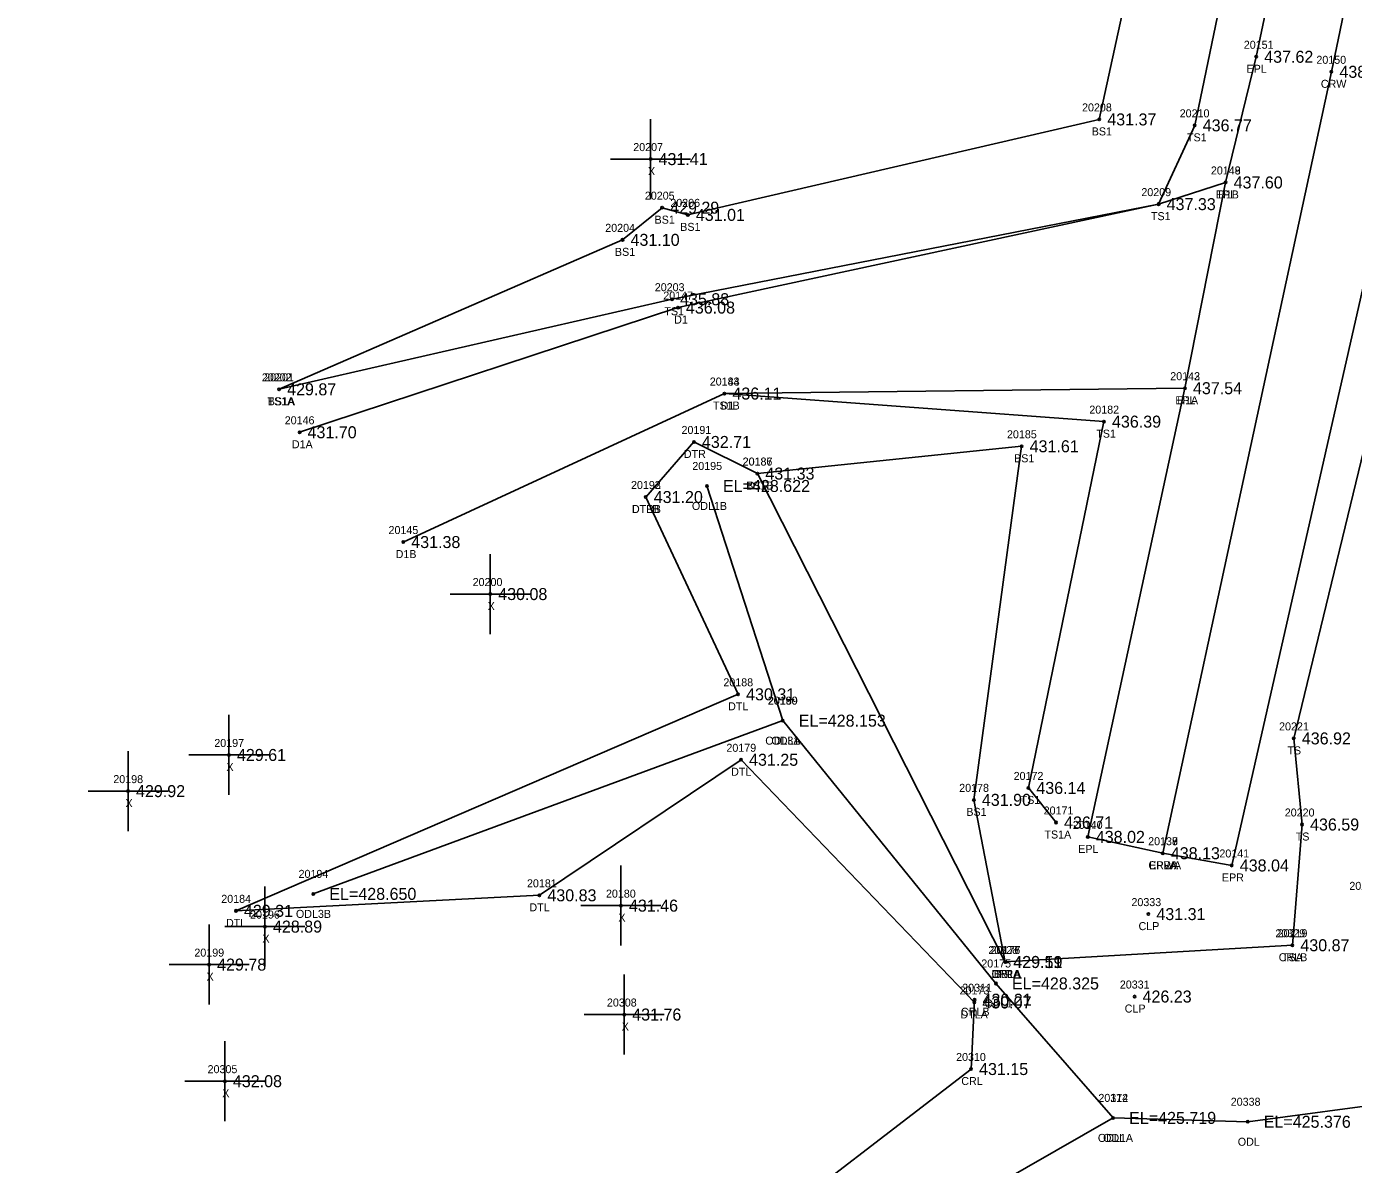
# Model space of a CAD drawing. Extents: x 1755707 to 1756750, y 975854 to 977363.
# Drawn here: x 1756070.3 to 1756236.1, y 976608 to 976750.2 of the extents above; entities that cross this region are included whole.
import ezdxf

# ---------------------------------------------------------------- set-up
doc = ezdxf.new("R2010")
doc.units = 0
for name, color, linetype in [('RD_DTM_BkLn1', 7, 'Continuous'), ('RD_DTM_BkLn2', 7, 'Continuous'), ('RD_DTM_BkLn_txCode', 7, 'Continuous'), ('RD_EX_Driveway', 7, 'Continuous'), ('RD_EX_Driveway_txCode', 7, 'Continuous'), ('RD_EX_H2O', 7, 'Continuous'), ('RD_EX_H2O_txCode', 7, 'Continuous'), ('RD_EX_Misc', 7, 'Continuous'), ('RD_EX_Misc_txCode', 7, 'Continuous'), ('RD_EX_Road', 7, 'Continuous'), ('RD_EX_Road_txCode', 7, 'Continuous'), ('RD_EX_TX_Driveway_ELEV', 7, 'Continuous'), ('RD_EX_TX_H2O_ELEV', 7, 'Continuous'), ('RD_EX_TX_Misc_ELEV', 7, 'Continuous'), ('RD_EX_TX_Road_ELEV', 7, 'Continuous'), ('RD_HC_Survey_ELEV', 7, 'Continuous'), ('RD_HC_Survey_txCode', 7, 'Continuous'), ('RD_SMD_Locator', 7, 'Continuous')]:
    doc.layers.add(name, color=color, linetype=linetype)

msp = doc.modelspace()

# ---------------------------------------------------------------- linework, layer by layer
at = {"layer": 'RD_DTM_BkLn1'}
msp.add_lwpolyline([(1756212.24, 976646.92), (1756233.31, 976744.58), (1756253.87, 976843.36), (1756274.18, 976942.87), (1756294.7, 977044.28), (1756314.7, 977141.54), (1756335.65, 977241.96), (1756357.9, 977342.03)], dxfattribs=at)
at = {"layer": 'RD_DTM_BkLn2'}
for points in [[(1756101.82, 976704.9), (1756150.92, 976716.16), (1756211.72, 976728.04), (1756216.23, 976737.89), (1756238.86, 976847.03), (1756261.79, 976945.44), (1756283.19, 977044.99), (1756303.06, 977145.95), (1756325.46, 977245.55), (1756346.55, 977344.09)], [(1756101.82, 976704.9), (1756144.73, 976723.58), (1756149.68, 976727.6), (1756152.89, 976726.7), (1756204.3, 976738.63), (1756228.54, 976849.91), (1756252.92, 976947.37), (1756266.62, 977008.29)], [(1756228.43, 976635.42), (1756229.64, 976650.51), (1756228.61, 976661.27), (1756248.15, 976741.84), (1756270.72, 976839.45), (1756280.12, 976897.48), (1756286.17, 976899.18), (1756290.15, 976895.42)], [(1756198.9, 976650.76), (1756195.44, 976655.08), (1756204.89, 976700.86), (1756157.46, 976704.37)], [(1756192.56, 976633.32), (1756188.63, 976653.59), (1756194.6, 976697.78), (1756161.58, 976694.37)]]:
    msp.add_lwpolyline(points, dxfattribs=at)
at = {"layer": 'RD_EX_Driveway'}
msp.add_line((1756211.72, 976728.04), (1756220.09, 976730.75), dxfattribs=at)
for points in [[(1756104.37, 976699.53), (1756151.65, 976715.11), (1756211.72, 976728.04)], [(1756215.01, 976705.04), (1756157.46, 976704.37), (1756117.33, 976685.81)]]:
    msp.add_lwpolyline(points, dxfattribs=at)
at = {"layer": 'RD_EX_H2O'}
for p, q in [((1756164.75, 976663.49), (1756106.09, 976641.84)), ((1756192.55, 976633.33), (1756228.43, 976635.42))]:
    msp.add_line(p, q, dxfattribs=at)
for points in [[(1756192.56, 976633.32), (1756161.58, 976694.37), (1756153.65, 976698.32), (1756147.63, 976691.44)], [(1756206.03, 976613.84), (1756191.39, 976630.64), (1756164.75, 976663.49), (1756155.28, 976692.82)], [(1756188.69, 976628.27), (1756159.54, 976658.6), (1756134.34, 976641.66), (1756096.42, 976639.72), (1756159.17, 976666.78), (1756147.63, 976691.44)], [(1755737.32, 976440.59), (1755791.96, 976465.24), (1755883.28, 976455.13), (1755971.27, 976482.19), (1756023.59, 976552.72), (1756109.16, 976576.08), (1756159.34, 976597.67), (1756188.28, 976619.95), (1756188.72, 976628.61)], [(1755742.06, 976428.66), (1755806.09, 976451.93), (1755887.6, 976439.2), (1755982.53, 976463.01), (1756033.69, 976542.66), (1756128.83, 976549.6), (1756169.54, 976582.49), (1756188.08, 976603.54), (1756206.03, 976613.84), (1756222.85, 976613.36), (1756242.15, 976615.93), (1756317.48, 976609.64), (1756394.89, 976590.11), (1756422.33, 976593.66), (1756518.23, 976582.93), (1756609.24, 976524.24), (1756704.51, 976490.62)]]:
    msp.add_lwpolyline(points, dxfattribs=at)
at = {"layer": 'RD_EX_Misc'}
for p, q in [((1756148.23, 976728.67), (1756148.23, 976738.67)), ((1756143.23, 976733.67), (1756153.23, 976733.67)), ((1756128.2, 976674.31), (1756128.2, 976684.31)), ((1756123.2, 976679.31), (1756133.2, 976679.31)), ((1756095.55, 976654.2), (1756095.55, 976664.2)), ((1756082.94, 976649.68), (1756082.94, 976659.68)), ((1756090.55, 976659.2), (1756100.55, 976659.2)), ((1756077.94, 976654.68), (1756087.94, 976654.68)), ((1756144.53, 976635.37), (1756144.53, 976645.37)), ((1756100.05, 976632.75), (1756100.05, 976642.75)), ((1756139.53, 976640.37), (1756149.53, 976640.37)), ((1756093.07, 976628), (1756093.07, 976638)), ((1756095.05, 976637.75), (1756105.05, 976637.75)), ((1756088.07, 976633), (1756098.07, 976633)), ((1756144.94, 976621.76), (1756144.94, 976631.76)), ((1756139.94, 976626.76), (1756149.94, 976626.76)), ((1756095.04, 976613.43), (1756095.04, 976623.43)), ((1756090.04, 976618.43), (1756100.04, 976618.43))]:
    msp.add_line(p, q, dxfattribs=at)
at = {"layer": 'RD_EX_Road'}
for points in [[(1756212.24, 976646.92), (1756202.87, 976648.96), (1756215.01, 976705.04), (1756220.09, 976730.75), (1756223.91, 976746.46), (1756244.6, 976844.81), (1756265.35, 976944.71), (1756286.1, 977045.83), (1756306.04, 977143.32), (1756326.71, 977243.79), (1756348.97, 977343.58)], [(1756212.24, 976646.92), (1756220.86, 976645.39), (1756242.73, 976741.74), (1756264.15, 976840.28), (1756284.31, 976940.54), (1756305.17, 977042.39), (1756325.03, 977140.07), (1756346.16, 977239.41), (1756368.47, 977341.2)]]:
    msp.add_lwpolyline(points, dxfattribs=at)
at = {"layer": 'RD_SMD_Locator'}
for centre in [(1756223.91, 976746.46), (1756233.31, 976744.58), (1756204.3, 976738.63), (1756216.23, 976737.89), (1756148.23, 976733.67), (1756220.09, 976730.75), (1756220.09, 976730.75), (1756211.72, 976728.04), (1756149.68, 976727.6), (1756152.89, 976726.7), (1756144.73, 976723.58), (1756150.92, 976716.16), (1756151.65, 976715.11), (1756101.82, 976704.9), (1756101.82, 976704.9), (1756215.01, 976705.04), (1756215.01, 976705.04), (1756157.46, 976704.37), (1756157.46, 976704.37), (1756204.89, 976700.86), (1756104.37, 976699.53), (1756153.65, 976698.32), (1756194.6, 976697.78), (1756161.58, 976694.37), (1756161.58, 976694.37), (1756147.63, 976691.44), (1756147.63, 976691.44), (1756155.28, 976692.82), (1756117.33, 976685.81), (1756128.2, 976679.31), (1756159.17, 976666.78), (1756164.75, 976663.49), (1756164.75, 976663.49), (1756228.61, 976661.27), (1756095.55, 976659.2), (1756159.54, 976658.6), (1756195.44, 976655.08), (1756082.94, 976654.68), (1756188.63, 976653.59), (1756198.9, 976650.76), (1756229.64, 976650.51), (1756202.87, 976648.96), (1756212.24, 976646.92), (1756212.24, 976646.92), (1756212.24, 976646.92), (1756220.86, 976645.39), (1756106.09, 976641.84), (1756134.34, 976641.66), (1756144.53, 976640.37), (1756096.42, 976639.72), (1756210.44, 976639.31), (1756100.05, 976637.75), (1756228.43, 976635.42), (1756228.43, 976635.42), (1756093.07, 976633), (1756192.55, 976633.33), (1756192.56, 976633.32), (1756192.56, 976633.32), (1756191.39, 976630.64), (1756188.72, 976628.61), (1756208.71, 976629.01), (1756188.69, 976628.27), (1756144.94, 976626.76), (1756188.28, 976619.95), (1756095.04, 976618.43), (1756206.03, 976613.84), (1756206.03, 976613.84), (1756222.85, 976613.36)]:
    msp.add_circle(centre, 0.15, dxfattribs=at)

# ---------------------------------------------------------------- texts
at = {"layer": 'RD_DTM_BkLn_txCode'}
for s, p in [('20208', (1756202.15, 976739.63)), ('20210', (1756214.35, 976738.89)), ('BS1', (1756203.36, 976736.63)), ('TS1', (1756215.27, 976735.89)), ('20209', (1756209.56, 976729.04)), ('20205', (1756147.52, 976728.6)), ('20206', (1756150.7, 976727.7)), ('BS1', (1756148.73, 976725.6)), ('TS1', (1756210.76, 976726.04)), ('20204', (1756142.57, 976724.58)), ('BS1', (1756151.94, 976724.7)), ('BS1', (1756143.78, 976721.58)), ('20203', (1756148.76, 976717.16)), ('TS1', (1756149.96, 976714.16)), ('20202', (1756099.66, 976705.9)), ('20201', (1756099.95, 976705.9)), ('20183', (1756155.63, 976705.37)), ('TS1A', (1756100.37, 976702.9)), ('BS1A', (1756100.39, 976702.9)), ('TS1B', (1756156.03, 976702.37)), ('20182', (1756203.06, 976701.86)), ('TS1', (1756203.93, 976698.86)), ('20185', (1756192.77, 976698.78)), ('BS1', (1756193.66, 976695.78)), ('20186', (1756159.73, 976695.37)), ('BS1B', (1756160.17, 976692.37)), ('20221', (1756226.77, 976662.27)), ('TS', (1756227.81, 976659.27)), ('20172', (1756193.6, 976656.08)), ('20178', (1756186.8, 976654.59)), ('TS1', (1756194.48, 976653.08)), ('BS1', (1756187.69, 976651.59)), ('20171', (1756197.35, 976651.76)), ('20220', (1756227.48, 976651.51)), ('TS1A', (1756197.45, 976648.76)), ('TS', (1756228.85, 976648.51)), ('20219', (1756226.59, 976636.42)), ('20176', (1756190.71, 976634.32)), ('TSA', (1756227.14, 976633.42)), ('BS1A', (1756191.13, 976631.32))]:
    msp.add_text(s, height=1, dxfattribs=at).set_placement(p)
at = {"layer": 'RD_EX_Driveway_txCode'}
for s, p in [('20148', (1756218.25, 976731.75)), ('D1B', (1756219.14, 976728.75)), ('20147', (1756149.82, 976716.11)), ('D1', (1756151.18, 976713.11)), ('20143', (1756213.17, 976706.04)), ('20144', (1756155.63, 976705.37)), ('D1', (1756156.99, 976702.37)), ('D1A', (1756214.05, 976703.04)), ('20146', (1756102.52, 976700.53)), ('D1A', (1756103.41, 976697.53)), ('20145', (1756115.49, 976686.81)), ('D1B', (1756116.38, 976683.81))]:
    msp.add_text(s, height=1, dxfattribs=at).set_placement(p)
at = {"layer": 'RD_EX_H2O_txCode'}
for s, p in [('20191', (1756152.1, 976699.32)), ('DTR', (1756152.39, 976696.32)), ('20195', (1756153.45, 976694.82)), ('20187', (1756159.75, 976695.37)), ('20192', (1756145.79, 976692.44)), ('20193', (1756145.79, 976692.44)), ('DTR', (1756160.32, 976692.37)), ('DTRB', (1756145.89, 976689.44)), ('DTLB', (1756145.91, 976689.44)), ('ODL1B', (1756153.4, 976689.82)), ('20188', (1756157.33, 976667.78)), ('DTL', (1756157.92, 976664.78)), ('20190', (1756162.87, 976665.49)), ('20189', (1756162.91, 976665.49)), ('20179', (1756157.71, 976659.6)), ('ODL3A', (1756162.57, 976660.49)), ('ODL1', (1756163.34, 976660.49)), ('DTL', (1756158.3, 976656.6)), ('20194', (1756104.25, 976643.84)), ('20181', (1756132.79, 976642.66)), ('20224', (1756235.55, 976642.34)), ('20184', (1756094.59, 976640.72)), ('DTL', (1756133.09, 976639.66)), ('DTL', (1756095.18, 976637.72)), ('ODL3B', (1756103.92, 976638.84)), ('20329', (1756226.31, 976636.42)), ('20328', (1756190.44, 976634.33)), ('20177', (1756190.73, 976634.32)), ('20175', (1756189.56, 976632.64)), ('CRLB', (1756226.73, 976633.42)), ('CRLA', (1756190.84, 976631.33)), ('DTRA', (1756190.81, 976631.32)), ('20173', (1756186.85, 976629.27)), ('20311', (1756187.17, 976629.61)), ('ODL1', (1756189.98, 976627.64)), ('DTLA', (1756186.95, 976626.27)), ('CRLB', (1756187.02, 976626.61)), ('20310', (1756186.41, 976620.95)), ('CRL', (1756187.06, 976617.95)), ('20174', (1756204.19, 976615.84)), ('20312', (1756204.19, 976615.84)), ('20338', (1756220.73, 976615.36)), ('ODL1A', (1756204.13, 976610.84)), ('ODL', (1756204.78, 976610.84)), ('ODL', (1756221.61, 976610.36))]:
    msp.add_text(s, height=1, dxfattribs=at).set_placement(p)
at = {"layer": 'RD_EX_Misc_txCode'}
for s, p in [('20207', (1756146.07, 976734.67)), ('X', (1756147.91, 976731.67)), ('20200', (1756126, 976680.31)), ('X', (1756127.88, 976677.31)), ('20197', (1756093.72, 976660.2)), ('X', (1756095.24, 976657.2)), ('20198', (1756081.1, 976655.68)), ('X', (1756082.62, 976652.68)), ('20180', (1756142.66, 976641.37)), ('20196', (1756098.19, 976638.75)), ('X', (1756144.21, 976638.37)), ('X', (1756099.73, 976635.75)), ('20199', (1756091.23, 976634)), ('X', (1756092.75, 976631)), ('20308', (1756142.78, 976627.76)), ('X', (1756144.63, 976624.76)), ('20305', (1756092.88, 976619.43)), ('X', (1756094.72, 976616.43))]:
    msp.add_text(s, height=1, dxfattribs=at).set_placement(p)
at = {"layer": 'RD_EX_Road_txCode'}
for s, p in [('20151', (1756222.36, 976747.46)), ('EPL', (1756222.7, 976744.46)), ('20149', (1756218.25, 976731.75)), ('EPL', (1756218.88, 976728.75)), ('20142', (1756213.17, 976706.04)), ('EPL', (1756213.8, 976703.04)), ('20140', (1756201, 976649.96)), ('20138', (1756210.41, 976647.92)), ('20139', (1756210.41, 976647.92)), ('EPL', (1756201.67, 976646.96)), ('20141', (1756219.31, 976646.39)), ('EPRA', (1756210.52, 976644.92)), ('EPLA', (1756210.55, 976644.92)), ('EPR', (1756219.63, 976643.39))]:
    msp.add_text(s, height=1, dxfattribs=at).set_placement(p)
at = {"layer": 'RD_EX_TX_Driveway_ELEV'}
for s, p in [('437.60', (1756221.09, 976730)), ('436.08', (1756152.65, 976714.36)), ('436.11', (1756158.46, 976703.62)), ('437.54', (1756216.01, 976704.29)), ('431.70', (1756105.37, 976698.78)), ('431.38', (1756118.33, 976685.06))]:
    msp.add_text(s, height=1.5, dxfattribs=at).set_placement(p)
at = {"layer": 'RD_EX_TX_H2O_ELEV'}
for s, p in [('432.71', (1756154.65, 976697.57)), ('431.33', (1756162.58, 976693.62)), ('EL=428.622', (1756157.28, 976692.07)), ('431.20', (1756148.63, 976690.69)), ('431.20', (1756148.63, 976690.69)), ('430.31', (1756160.17, 976666.03)), ('EL=428.153', (1756166.75, 976662.74)), ('EL=428.153', (1756166.75, 976662.74)), ('431.25', (1756160.54, 976657.85)), ('EL=428.650', (1756108.09, 976641.09)), ('430.83', (1756135.34, 976640.91)), ('429.31', (1756097.42, 976638.97)), ('430.87', (1756229.43, 976634.67)), ('429.11', (1756193.55, 976632.58)), ('429.59', (1756193.56, 976632.57)), ('EL=428.325', (1756193.39, 976629.89)), ('430.07', (1756189.69, 976627.52)), ('430.21', (1756189.72, 976627.86)), ('431.15', (1756189.28, 976619.2)), ('EL=425.719', (1756208.03, 976613.09)), ('EL=425.719', (1756208.03, 976613.09)), ('EL=425.376', (1756224.85, 976612.61))]:
    msp.add_text(s, height=1.5, dxfattribs=at).set_placement(p)
at = {"layer": 'RD_EX_TX_Misc_ELEV'}
for s, p in [('431.37', (1756205.3, 976737.88)), ('436.77', (1756217.23, 976737.14)), ('431.41', (1756149.23, 976732.92)), ('429.29', (1756150.68, 976726.85)), ('437.33', (1756212.72, 976727.29)), ('431.01', (1756153.89, 976725.95)), ('431.10', (1756145.73, 976722.83)), ('435.88', (1756151.92, 976715.41)), ('429.87', (1756102.82, 976704.15)), ('429.87', (1756102.82, 976704.15)), ('436.11', (1756158.46, 976703.62)), ('436.39', (1756205.89, 976700.11)), ('431.61', (1756195.6, 976697.03)), ('431.33', (1756162.58, 976693.62)), ('430.08', (1756129.2, 976678.56)), ('436.92', (1756229.61, 976660.52)), ('429.61', (1756096.55, 976658.45)), ('429.92', (1756083.94, 976653.93)), ('436.14', (1756196.44, 976654.33)), ('431.90', (1756189.63, 976652.84)), ('436.71', (1756199.9, 976650.01)), ('436.59', (1756230.64, 976649.76)), ('431.46', (1756145.53, 976639.62)), ('428.89', (1756101.05, 976637)), ('430.87', (1756229.43, 976634.67)), ('429.78', (1756094.07, 976632.25)), ('429.59', (1756193.56, 976632.57)), ('431.76', (1756145.94, 976626.01)), ('432.08', (1756096.04, 976617.68))]:
    msp.add_text(s, height=1.5, dxfattribs=at).set_placement(p)
at = {"layer": 'RD_EX_TX_Road_ELEV'}
for s, p in [('437.62', (1756224.91, 976745.71)), ('437.60', (1756221.09, 976730)), ('437.54', (1756216.01, 976704.29)), ('438.02', (1756203.87, 976648.21)), ('438.13', (1756213.24, 976646.17)), ('438.13', (1756213.24, 976646.17)), ('438.04', (1756221.86, 976644.64))]:
    msp.add_text(s, height=1.5, dxfattribs=at).set_placement(p)
at = {"layer": 'RD_HC_Survey_ELEV'}
for s, p in [('438.05', (1756234.31, 976743.83)), ('438.13', (1756213.24, 976646.17)), ('431.31', (1756211.44, 976638.56)), ('426.23', (1756209.71, 976628.26))]:
    msp.add_text(s, height=1.5, dxfattribs=at).set_placement(p)
at = {"layer": 'RD_HC_Survey_txCode'}
for s, p in [('20150', (1756231.43, 976745.58)), ('CRW', (1756231.99, 976742.58)), ('20137', (1756210.41, 976647.92)), ('CRWA', (1756210.44, 976644.92)), ('20333', (1756208.32, 976640.31)), ('CLP', (1756209.21, 976637.31)), ('20331', (1756206.87, 976630.01)), ('CLP', (1756207.48, 976627.01))]:
    msp.add_text(s, height=1, dxfattribs=at).set_placement(p)

doc.saveas('drawing.dxf')
